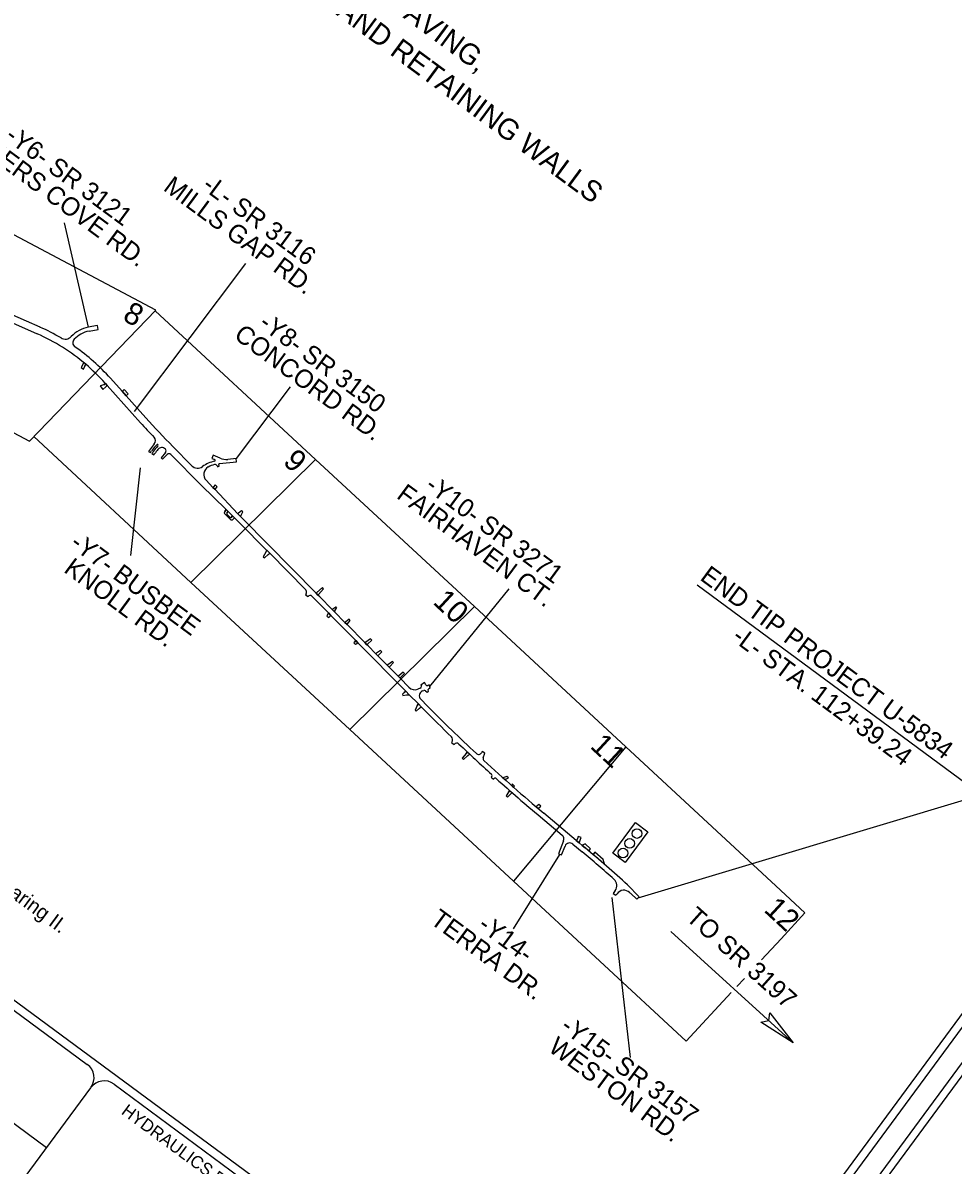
# Model space of a CAD drawing. Extents: x 945666 to 965748, y 644452 to 663300.
# Drawn here: x 956642 to 962231, y 648072 to 654930 of the extents above; entities that cross this region are included whole.
import ezdxf

# ---------------------------------------------------------------- set-up
doc = ezdxf.new("R2010")
doc.units = 0
for name, color, linetype in [('Old_Level_23', 7, 'Continuous'), ('Prop EOT', 7, 'Continuous'), ('Prop PHM Traffic Signal CELL', 7, 'Continuous'), ('Prop Shade Light', 7, 'Continuous'), ('Prop Terminator CELL', 7, 'Continuous'), ('Sheet Data Field CELL', 7, 'Continuous'), ('Sheet Plan Layout CELL', 7, 'Continuous'), ('Sheet Plot Border Inside CELL', 7, 'Continuous'), ('Sheet Plot Border Outside CELL', 7, 'Continuous'), ('Sheet Title CELL', 7, 'Continuous')]:
    doc.layers.add(name, color=color, linetype=linetype)

msp = doc.modelspace()

# ---------------------------------------------------------------- linework, layer by layer
at = {"layer": 'Old_Level_23'}
for p, q in [((956889.9, 653730), (957035, 653102.4)), ((957979.3, 653485.3), (957310.1, 652597.3)), ((958247.3, 652744.8), (957923.2, 652314.7)), ((957347.4, 652259), (957289.4, 651732.8)), ((959561.1, 651532.1), (959085.7, 650945.3)), ((959590.4, 649490.6), (959867.5, 649936)), ((960293.3, 648719.1), (960182.8, 649678.4)), ((960534.7, 649473.8), (961270.1, 648807.2))]:
    msp.add_line(p, q, dxfattribs=at)
msp.add_lwpolyline([(960337.8, 649676.2), (962398, 650295.8), (960692.6, 651553.5)], dxfattribs=at)
at = {"layer": 'Prop EOT'}
for p, q in [((957002.3, 652878.7), (957008.2, 652890.1)), ((957014.5, 652868.4), (957020.5, 652880)), ((957129.1, 652756.3), (957138.4, 652764.6)), ((957139.8, 652744.4), (957148.9, 652752.9)), ((957241.9, 652721.2), (957238.2, 652717.9)), ((957266, 652694.4), (957262.4, 652690.9)), ((957787.5, 652144.7), (957784, 652141.2)), ((957798.5, 652133.1), (957794.9, 652129.6)), ((957856.4, 651996.5), (957863, 652007.5)), ((957867.9, 651985.3), (957874.7, 651996.2)), ((957893.1, 651960.8), (957902.2, 651969.4)), ((957904.6, 651949.6), (957914.2, 651957.7)), ((957938.4, 651985.6), (957934.4, 651982.5)), ((957952.1, 651971.1), (957949.5, 651966.6)), ((958101.4, 651751.6), (958107.4, 651763.3)), ((958115.5, 651737.4), (958125.3, 651745.2)), ((958407.2, 651509.5), (958403.2, 651506.5)), ((958418.5, 651498.1), (958415.1, 651494.4)), ((958472.9, 651375.3), (958479.1, 651386.9)), ((958505, 651410.5), (958500.5, 651407.9)), ((958516.2, 651399.1), (958513.5, 651394.8)), ((958484.2, 651363.9), (958493, 651372.8)), ((958581.4, 651333.2), (958577.2, 651330.3)), ((958592.7, 651321.8), (958589.5, 651317.8)), ((958634, 651212.2), (958641.5, 651222.5)), ((958645.3, 651200.8), (958655.3, 651208.4)), ((958701.7, 651211.3), (958697.1, 651208.8)), ((958712.9, 651199.9), (958709.2, 651196.5)), ((958767.4, 651144.8), (958763.1, 651142)), ((958778.6, 651133.4), (958775.3, 651129.6)), ((958834.8, 651076.5), (958830.6, 651073.6)), ((958846.1, 651065.1), (958843.1, 651060.9)), ((958899.9, 651010.5), (958896.1, 651007.3)), ((958911.2, 650999.1), (958908, 650995.2)), ((958933.5, 650909), (958942, 650918.2)), ((958947.5, 650894.7), (958963.5, 650896.4)), ((959010.9, 650830.6), (959018, 650841.1)), ((959024.9, 650816.3), (959034.6, 650824.3)), ((959304.3, 650542.9), (959312.2, 650552.6)), ((959315.9, 650532), (959325.4, 650540.2)), ((959531.4, 650399.1), (959526, 650397.3)), ((959543.4, 650388.4), (959538.4, 650386.2)), ((959559.7, 650310.6), (959566.5, 650321.3)), ((959571.7, 650300.1), (959580.8, 650308.7)), ((959580.8, 650355.4), (959578.4, 650350.8)), ((959592.8, 650344.8), (959589, 650341.4)), ((959729.9, 650226.5), (959725.9, 650223.4)), ((959742.1, 650216.2), (959738.6, 650212.6)), ((959970.3, 650025.5), (959966.8, 650021.7)), ((959985.5, 650012.5), (959983.8, 650007.4)), ((960007.3, 649994.3), (960002.6, 649991.7)), ((960045.6, 649962.2), (960042.7, 649958)), ((960070.2, 649941.4), (960066.7, 649937.7)), ((960134.6, 649885.9), (960137, 649877.4))]:
    msp.add_line(p, q, dxfattribs=at)
at = {"layer": 'Prop PHM Traffic Signal CELL'}
for p, q in [((960186.2, 649944.1), (960322.1, 650128.4)), ((960322.1, 650128.4), (960396.6, 650073.5)), ((960396.6, 650073.5), (960260.7, 649889.2)), ((960260.7, 649889.2), (960186.2, 649944.1))]:
    msp.add_line(p, q, dxfattribs=at)
for centre in [(960331.1, 650062.6), (960287.6, 650003.6), (960247.5, 649945.5)]:
    msp.add_circle(centre, 28.8, dxfattribs=at)
at = {"layer": 'Prop Shade Light'}
for p, q in [((955896.2, 653431.8), (956727.8, 653063.6)), ((956745.2, 653103), (956582.5, 653175)), ((957090, 653113.1), (957035, 653102.5)), ((957094.6, 653089.6), (957090, 653113.1)), ((957039.5, 653078.9), (957094.6, 653089.6)), ((957002.3, 652878.7), (956993.2, 652861.5)), ((957008.2, 652890.1), (957002.3, 652878.7)), ((957014.5, 652868.4), (957020.4, 652879.8)), ((957020.5, 652880), (957020.4, 652879.8)), ((957138.3, 652764.7), (957129.1, 652756.3)), ((957148.8, 652753), (957138.3, 652764.7)), ((957129.1, 652756.3), (957106.4, 652751.1)), ((957106.4, 652751.1), (957123.3, 652729.6)), ((957123.3, 652729.6), (957139.8, 652744.4)), ((957139.8, 652744.4), (957148.8, 652753)), ((957241.9, 652721.2), (957238.2, 652717.9)), ((957238.2, 652717.9), (957262.4, 652690.9)), ((957250.3, 652728.7), (957241.9, 652721.2)), ((957274.3, 652702), (957250.3, 652728.7)), ((957262.4, 652690.9), (957265.9, 652694.4)), ((957265.9, 652694.4), (957274.3, 652702)), ((957402.4, 652364), (957397.9, 652357.4)), ((957397.9, 652357.4), (957409.4, 652349.5)), ((957409.4, 652349.5), (957413.9, 652356.1)), ((957422.2, 652350.5), (957417.7, 652343.9)), ((957431.5, 652401.6), (957427.4, 652396.7)), ((957438, 652387.7), (957446.2, 652397.2)), ((957453.8, 652390.7), (957445.6, 652381.2)), ((957499.2, 652351.2), (957473.1, 652318.5)), ((957657, 652271.4), (957542.8, 652387)), ((957417.7, 652343.9), (957429.2, 652336)), ((957429.2, 652336), (957433.8, 652342.6)), ((957473.1, 652318.5), (957480.8, 652310.7)), ((957480.8, 652310.7), (957509.1, 652338.6)), ((957530.3, 652338.5), (957712.8, 652153.7)), ((957786.1, 652334.9), (957776.7, 652313.6)), ((957776.7, 652313.6), (957794.4, 652308.6)), ((957827, 652317), (957786.1, 652334.9)), ((957820.7, 652267.8), (957818.7, 652277.8)), ((957823, 652283.8), (957925.3, 652294.8)), ((957923.2, 652314.7), (957874.1, 652309.4)), ((957925.3, 652294.8), (957923.2, 652314.7)), ((957811, 652268.4), (957812.1, 652265.3)), ((957812.1, 652265.3), (957820.7, 652267.8)), ((957787.4, 652144.7), (957783.9, 652141.2)), ((957783.9, 652141.2), (957794.9, 652129.6)), ((957798.3, 652155.5), (957787.4, 652144.7)), ((957809.5, 652144.1), (957798.3, 652155.5)), ((957798.5, 652133.1), (957809.5, 652144.1)), ((957794.9, 652129.6), (957798.5, 652133.1)), ((957863, 652007.5), (957856.4, 651996.5)), ((957874.7, 651996.2), (957863, 652007.5)), ((957856.4, 651996.5), (957850.6, 651987.1)), ((957850.6, 651987.1), (957887.7, 651949.6)), ((957867.9, 651985.3), (957874.7, 651996.2)), ((957887.9, 651960.8), (957867.9, 651981)), ((957902.2, 651969.4), (957893.1, 651960.8)), ((957914.2, 651957.7), (957902.2, 651969.4)), ((957904.6, 651949.6), (957914.2, 651957.7)), ((957938.4, 651985.7), (957934.4, 651982.6)), ((957934.4, 651982.6), (957949.5, 651966.6)), ((957949.5, 651966.6), (957952.1, 651971.1)), ((957945.7, 651927), (958105.8, 651764.9)), ((958107.4, 651763.3), (958101.4, 651751.6)), ((958125.2, 651745.3), (958107.4, 651763.3)), ((958115.5, 651737.4), (958125.2, 651745.3)), ((958441.2, 651539.3), (958407.2, 651509.5)), ((958418.5, 651498.1), (958447.8, 651532.3)), ((958447.8, 651532.3), (958441.2, 651539.3)), ((958344.4, 651502.8), (958341, 651496.6)), ((958341, 651496.6), (958355.9, 651486.3)), ((958378.9, 651488.4), (958457.8, 651408.4)), ((958407.2, 651509.5), (958403.2, 651506.5)), ((958403.2, 651506.5), (958415.1, 651494.4)), ((958415.1, 651494.4), (958418.5, 651498.1)), ((958479.1, 651387), (958472.9, 651375.4)), ((958493, 651372.8), (958479.1, 651387)), ((958505, 651410.5), (958500.5, 651408)), ((958500.5, 651408), (958513.4, 651394.8)), ((958513.4, 651394.8), (958516.2, 651399.1)), ((958516.2, 651399.1), (958528.8, 651418.9)), ((958484.2, 651364), (958493, 651372.8)), ((958581.4, 651333.2), (958577.1, 651330.3)), ((958577.1, 651330.3), (958589.5, 651317.8)), ((958602.5, 651348.9), (958581.4, 651333.2)), ((958589.5, 651317.8), (958592.6, 651321.9)), ((958592.6, 651321.9), (958609.1, 651342.8)), ((958609.1, 651342.8), (958602.5, 651348.9)), ((958634, 651212.2), (958630.8, 651207.5)), ((958641.4, 651222.5), (958634, 651212.2)), ((958655.3, 651208.4), (958641.4, 651222.5)), ((958645.3, 651200.8), (958655.3, 651208.4)), ((958701.6, 651211.3), (958697.1, 651208.8)), ((958697.1, 651208.8), (958709.2, 651196.6)), ((958730, 651230.9), (958701.6, 651211.3)), ((958709.2, 651196.6), (958712.9, 651200)), ((958712.9, 651200), (958737.5, 651223.2)), ((958737.5, 651223.2), (958730, 651230.9)), ((958767.4, 651144.8), (958763.1, 651142)), ((958763.1, 651142), (958775.3, 651129.7)), ((958791.2, 651161.4), (958767.4, 651144.8)), ((958775.3, 651129.7), (958778.6, 651133.4)), ((958778.6, 651133.4), (958799.4, 651153.1)), ((958799.4, 651153.1), (958791.2, 651161.4)), ((958834.8, 651076.5), (958830.6, 651073.7)), ((958830.6, 651073.7), (958843.1, 651061)), ((958862.7, 651096.5), (958834.8, 651076.5)), ((958843.1, 651061), (958846.1, 651065.1)), ((958846.1, 651065.1), (958868.5, 651090.6)), ((958868.5, 651090.6), (958862.7, 651096.5)), ((958899.9, 651010.5), (958896.1, 651007.3)), ((958896.1, 651007.3), (958908, 650995.2)), ((958926.3, 651032), (958899.9, 651010.5)), ((958908, 650995.2), (958911.2, 650999.2)), ((958911.2, 650999.2), (958934.7, 651023.5)), ((958934.7, 651023.5), (958926.3, 651032)), ((958933.4, 650909), (958923.6, 650899.7)), ((958941.9, 650918.2), (958933.4, 650909)), ((958963.4, 650896.4), (958941.9, 650918.2)), ((959029.7, 650935.2), (959014.2, 650929.5)), ((959054.5, 650969), (959033.5, 650953.2)), ((959033.5, 650953.2), (959035.9, 650947.2)), ((959043, 650918.8), (959051.4, 650921.9)), ((959062.6, 650955.9), (959054.5, 650969)), ((959061.1, 650920.4), (959070.1, 650911.3)), ((959070.1, 650911.3), (959079.8, 650916.1)), ((959082.2, 650954.7), (959074.6, 650951.9)), ((959079.8, 650916.1), (959076.8, 650927.2)), ((959080, 650932.6), (959089.1, 650935.9)), ((959089.1, 650935.9), (959082.2, 650954.7)), ((958923.6, 650899.7), (958925.5, 650892.1)), ((958925.5, 650892.1), (958947.5, 650894.8)), ((958947.5, 650894.8), (958963.4, 650896.4)), ((959018, 650841.2), (959010.9, 650830.6)), ((959034.6, 650824.3), (959018, 650841.2)), ((959073.1, 650828.1), (959032.1, 650869.6)), ((959004.9, 650798.3), (959024.9, 650816.4)), ((959024.9, 650816.4), (959034.6, 650824.3)), ((959219.6, 650611.9), (959217.6, 650608.9)), ((959217.6, 650608.9), (959232.2, 650597.9)), ((959304.3, 650543), (959280.9, 650515.8)), ((959290.1, 650507.6), (959315.9, 650532)), ((959312.2, 650552.6), (959304.3, 650543)), ((959315.9, 650532), (959325.4, 650540.2)), ((959401.2, 650554.9), (959397.6, 650548.2)), ((959416.6, 650545), (959401.2, 650554.9)), ((959407.6, 650516.6), (959416.6, 650545)), ((959458.5, 650404.3), (959455.7, 650401.1)), ((959455.7, 650401.1), (959469.3, 650389.3)), ((959469.3, 650389.3), (959471.7, 650392.1)), ((959531.4, 650399.1), (959526, 650397.3)), ((959548.9, 650404.8), (959531.4, 650399.1)), ((959538.4, 650386.2), (959543.4, 650388.4)), ((959543.4, 650388.4), (959559.3, 650396.8)), ((959559.3, 650396.8), (959548.9, 650404.8)), ((959559.7, 650310.7), (959545.1, 650288.7)), ((959566.5, 650321.3), (959559.7, 650310.7)), ((959571.7, 650300.1), (959580.8, 650308.7)), ((959580.7, 650355.4), (959578.4, 650350.8)), ((959589, 650341.4), (959592.8, 650344.8)), ((959729.9, 650226.6), (959725.9, 650223.4)), ((959741.6, 650237.6), (959729.9, 650226.6)), ((959738.6, 650212.6), (959742.1, 650216.2)), ((959751.6, 650162.5), (959882, 650053.4)), ((959890.6, 650019.1), (959859, 649941.7)), ((959970.2, 650025.5), (959966.7, 650021.7)), ((959966.7, 650021.7), (959983.8, 650007.4)), ((959995.6, 650039.6), (959978.4, 650045.5)), ((959985.5, 650012.6), (959995.6, 650039.6)), ((959877.5, 649934.1), (959899.4, 649987.9)), ((959946.5, 649999.5), (960001.4, 649953.6)), ((959983.8, 650007.4), (959985.5, 650012.6)), ((960007.2, 649994.3), (960002.6, 649991.7)), ((960002.6, 649991.7), (960020.6, 649976.6)), ((960019.3, 650000.1), (960007.2, 649994.3)), ((960052.8, 649971.4), (960019.3, 650000.1)), ((960042.7, 649958.1), (960045.6, 649962.2)), ((960045.6, 649962.2), (960052.8, 649971.4)), ((960077.7, 649950), (960070.2, 649941.4)), ((960127.8, 649907), (960077.7, 649950)), ((959859, 649941.7), (959877.5, 649934.1)), ((960070.2, 649941.4), (960066.7, 649937.8)), ((960134.6, 649886), (960127.8, 649907)), ((960136.9, 649877.4), (960134.6, 649886)), ((960344.7, 649683.7), (960274.5, 649754.9)), ((960200.9, 649720.7), (960188.6, 649703.8)), ((960188.6, 649703.8), (960204.8, 649692)), ((960204.8, 649692), (960211.8, 649701.6)), ((960293.7, 649702.1), (960330.9, 649668.9)), ((960330.9, 649668.9), (960344.7, 649683.7))]:
    msp.add_line(p, q, dxfattribs=at)
for points in [[(956993.2, 652861.5), (957007.2, 652851.1), (957014.5, 652868.4)], [(957020.4, 652879.9), (957020.5, 652880)], [(957135.9, 652767.4), (957138.3, 652764.7), (957148.8, 652753), (957349.6, 652529.5)], [(957381.5, 652558.3), (957262.4, 652690.9), (957238.2, 652717.9), (957167.9, 652796.1)], [(957498.2, 652371.1), (957498.3, 652371)], [(957712.8, 652153.7), (957863, 652007.5), (957874.7, 651996.2), (957902.2, 651969.4), (957914.2, 651957.7), (957945.7, 651927)], [(957967.1, 651948.1), (957949.5, 651966.6), (957934.4, 651982.6), (957794.9, 652129.6), (957783.9, 652141.2), (957743.4, 652183.9)], [(957783.9, 652141.2), (957783.9, 652141.2)], [(957952.1, 651971.1), (957964.1, 651994), (957955.9, 651999.8), (957938.4, 651985.7)], [(958425.5, 651483.9), (958415.1, 651494.4), (958403.2, 651506.5), (957967.1, 651948.1)], [(958101.4, 651751.6), (958086.7, 651723.6), (958092.8, 651718.5), (958115.5, 651737.4)], [(958105.8, 651764.9), (958107.4, 651763.3), (958125.2, 651745.3), (958341.2, 651526.6)], [(958589.5, 651317.8), (958577.1, 651330.3), (958513.4, 651394.8), (958500.5, 651408), (958425.5, 651483.9)], [(958457.8, 651408.4), (958479.1, 651387), (958493, 651372.8), (958641.4, 651222.5), (958655.3, 651208.4), (958941.9, 650918.2), (958963.4, 650896.4), (959018, 650841.2), (959034.6, 650824.3), (959051.8, 650807)], [(958528.8, 651418.9), (958521.9, 651422.5), (958505, 651410.5)], [(958472.9, 651375.4), (958468.8, 651367.4), (958479.2, 651359.4), (958484.2, 651364)], [(958716.4, 651189.3), (958709.2, 651196.6), (958697.1, 651208.8), (958589.5, 651317.8)], [(958630.8, 651207.5), (958640.1, 651197.9), (958645.3, 651200.8)], [(958961.3, 650941.3), (958908, 650995.2), (958896.1, 651007.3), (958843.1, 651061), (958830.6, 651073.7), (958775.3, 651129.7), (958763.1, 651142), (958716.4, 651189.3)], [(959010.9, 650830.6), (958997.9, 650804), (959004.9, 650798.3)], [(959280.9, 650515.8), (959284.6, 650511.5), (959290.1, 650507.6)], [(959592.8, 650344.8), (959596.4, 650347.4), (959581, 650361.5), (959580.7, 650355.4)], [(959545.1, 650288.7), (959553.5, 650281.9), (959571.7, 650300.1)], [(959742.1, 650216.2), (959753.8, 650227.3), (959741.6, 650237.6)], [(960020.6, 649976.6), (960002.6, 649991.7), (959983.8, 650007.4), (959966.7, 650021.7), (959770.9, 650185.6)]]:
    msp.add_lwpolyline(points, dxfattribs=at)
for centre, radius, start, end in [((956240.5, 651963.2), 1246.5, 59.59437, 66.11932), ((957071.5, 652914), 192, 100.975, 136.23687), ((956240.5, 651963.2), 1203.5, 49.61225, 66.11932), ((956896.7, 653081.4), 50, 239.59437, 316.23687), ((957071.5, 652914), 168, 100.975, 136.2327), ((956971.8, 653009.4), 30, 136.2327, 235.04773), ((956240.5, 651963.2), 1246.5, 41.93071, 55.04773), ((956240.5, 651963.2), 1203.5, 49.60968, 50.37119), ((956240.5, 651963.2), 1203.5, 41.93071, 49.60968), ((961085.3, 655885), 4978.5, 221.93071, 224.63859), ((961085.3, 655885), 5021.5, 221.93071, 223.2943), ((957408.6, 652421), 30, 319.6, 43.2943), ((957723.6, 652144.6), 389, 139.6, 145.66667), ((957723.6, 652144.6), 375, 139.6, 145.66667), ((957723.6, 652144.6), 365, 139.6, 145.66667), ((957723.6, 652144.6), 351, 140.22989, 145.66667), ((957450, 652394), 5, 319.6, 139.6), ((957476.9, 652350), 30, 44.61179, 140.22989), ((957487.5, 652360.6), 15, 44.12626, 44.40966), ((957476.9, 652350), 30, 44.4117, 44.61179), ((957487.5, 652360.6), 15, 321.50181, 44.12626), ((957519.6, 652327.9), 15, 44.63859, 134.59178), ((957843.5, 652094.8), 210, 103.58043, 125.48912), ((957843.5, 652094.8), 190, 105.46909, 117.46274), ((957796.8, 652263.5), 15, 18.91701, 105.46909), ((957793, 652303.8), 5, 283.58043, 74.24747), ((957823.6, 652278.8), 5, 96.42397, 191.37306), ((957864.4, 652398.9), 90, 245.40579, 276.18333), ((957692.6, 652306.5), 50, 224.63859, 305.48912), ((957778.9, 652219.1), 50, 117.46274, 224.63859), ((957870.1, 651983.2), 3.12, 135.78436, 224.63859), ((957896.1, 651957.9), 11.8, 224.63859, 315.78436), ((957890.5, 651963.4), 3.69, 224.63859, 315.78436), ((958326.9, 651512.5), 20, 330.7607, 44.63859), ((958368.2, 651477.8), 15, 44.63859, 145.45268), ((958996.9, 650976.4), 50, 224.63859, 290.31711), ((959053.4, 650890.7), 30, 110.31711, 224.63859), ((959026.2, 650944.6), 10, 290.31711, 15.019), ((959054.8, 650912.6), 10, 51.42192, 110.31711), ((959071.1, 650961.2), 10, 212.07076, 290.31711), ((959081.8, 650927.9), 5, 110.31711, 187.71299), ((966178, 657843.8), 10015, 224.63859, 225.9637), ((966178, 657843.8), 9985, 224.63859, 226.98518), ((959199, 650626.1), 25, 325.51934, 45.9637), ((959248.1, 650585.8), 20, 46.32509, 142.96717), ((966178, 657843.8), 10015, 226.32509, 227.85403), ((966178, 657843.8), 10015, 226.72127, 226.82512), ((959380, 650557.7), 20, 226.98518, 331.90862), ((959421.8, 650512), 15, 162.28522, 227.34006), ((966178, 657843.8), 9985, 227.34006, 230.08333), ((959451, 650410.9), 10, 318.83333, 47.85403), ((959479.2, 650385.5), 10, 48.07123, 138.83333), ((966178, 657843.8), 10015, 228.07123, 230.08333), ((966178, 657843.8), 9985, 228.22565, 228.32103), ((966178, 657843.8), 10015, 228.68811, 228.7973), ((966178, 657843.8), 9985, 228.62739, 228.70893), ((966178, 657843.8), 9985, 229.74594, 229.84179), ((959862.8, 650030.4), 30, 337.7936, 50.08333), ((959948.4, 650046), 30, 316.83583, 359.09599), ((959927.2, 649976.5), 30, 50.08333, 157.7936), ((954877.6, 643829.3), 7985, 48.25902, 50.08333), ((954877.6, 643829.3), 8015, 47.67351, 50.08333), ((954877.6, 643829.3), 8015, 49.87729, 50.08333), ((954877.6, 643829.3), 8015, 48.99034, 49.65257), ((960160.5, 649750.1), 50, 324.0667, 48.25902), ((960252.3, 649672.3), 50, 47.39074, 144.0667), ((954877.6, 643829.3), 7989, 47.31687, 47.39074)]:
    msp.add_arc(centre, radius, start, end, dxfattribs=at)
at = {"layer": 'Prop Terminator CELL'}
msp.add_lwpolyline([(961129.4, 648987), (961270.1, 648807.2), (961075.6, 648929.5), (961123.8, 648939.9)], close=True, dxfattribs=at)
at = {"layer": 'Sheet Plan Layout CELL'}
for p, q in [((957441.2, 653205.6), (956320.5, 653797.4)), ((957441.2, 653205.6), (956681.5, 652419.4)), ((958399.9, 652309.4), (957436.9, 653201.2)), ((955894.4, 652835), (956681.5, 652419.4)), ((956707.1, 652446), (957652.1, 651570.9)), ((958399.9, 652309.4), (957652.1, 651570.9)), ((959354.7, 651425.3), (958399.9, 652309.4)), ((957652.1, 651570.9), (958606.8, 650686.8)), ((959354.7, 651425.3), (958606.8, 650686.8)), ((960263.7, 650583.5), (959354.7, 651425.3)), ((958606.8, 650686.8), (959589.1, 649777.2)), ((960263.7, 650583.5), (959589.1, 649777.2)), ((961164.9, 649749), (960263.7, 650583.5)), ((959589.1, 649777.2), (960627, 648816)), ((961340.5, 649586.4), (961164.9, 649749)), ((961196.8, 649431.2), (961340.5, 649586.4)), ((961079, 649304.1), (961196.8, 649431.2)), ((960627, 648816), (960897.5, 649108))]:
    msp.add_line(p, q, dxfattribs=at)
msp.add_lwpolyline([(960930.4, 649143.6), (960976.2, 649193.1)], dxfattribs=at)
at = {"layer": 'Sheet Plot Border Inside CELL'}
msp.add_lwpolyline([(945903.9, 654551), (959315.9, 644659.5), (965578.4, 653150.9), (952166.4, 663042.4)], close=True, dxfattribs=at)
at = {"layer": 'Sheet Plot Border Outside CELL'}
msp.add_lwpolyline([(965747.9, 653304.9), (952195, 663300.2), (945666.1, 654447.6), (959218.9, 644452.2)], close=True, dxfattribs=at)
at = {"layer": 'Sheet Title CELL'}
for p, q in [((948809.3, 654800.8), (960237.5, 646372.5)), ((954735.2, 650368.4), (957028.9, 648676.7)), ((956784.3, 648176.7), (954329.7, 649987.1)), ((956100.2, 647249.1), (957049.9, 648536.8)), ((957189.8, 648558), (958797.6, 647372.3))]:
    msp.add_line(p, q, dxfattribs=at)
for points in [[(959289.8, 644834.8), (965403.3, 653124.1)], [(960377.3, 646393.5), (965333.4, 653113.7)]]:
    msp.add_lwpolyline(points, dxfattribs=at)
for centre, start, end in [((956969.8, 648596.6), 323.59084, 53.59084), ((957130.8, 648477.9), 53.59084, 143.59084)]:
    msp.add_arc(centre, 100, start, end, dxfattribs=at)

# ---------------------------------------------------------------- texts
at = {"layer": 'Old_Level_23'}
for s, rotation, p in [('PINNERS COVE RD.', 323.59084, (956205.2, 654293)), ('-Y6- SR 3121', 323.59084, (956529.1, 654233.4)), ('MILLS GAP RD.', 323.59084, (957480.1, 653928.9)), ('-L- SR 3116', 323.59084, (957712, 653937)), ('CONCORD RD.', 323.59084, (957903.8, 653040.3)), ('-Y8- SR 3150', 323.59084, (958052.8, 653109.6)), ('FAIRHAVEN CT.', 323.59084, (958881.1, 652081)), ('-Y10- SR 3271', 323.59084, (959051.8, 652134.4)), ('-Y7- BUSBEE', 323.59084, (956919, 651788.8)), ('KNOLL RD.', 323.59084, (956882, 651636.9)), (' END TIP PROJECT U-5834', 323.59084, (960671.1, 651613.9)), ('-L- STA. 112+39.24', 323.59084, (960895.2, 651226.6)), ('TERRA DR.', 323.59084, (959082.8, 649527.7)), ('TO SR 3197', 318.19631, (960619.5, 649549.3)), ('-Y14-', 323.59084, (959368.7, 649496.1)), ('-Y15- SR 3157', 323.59084, (959864.6, 648887.2)), ('WESTON RD.', 323.59084, (959791.6, 648761.8))]:
    msp.add_text(s, height=110, rotation=rotation, dxfattribs=at).set_placement(p)
at = {"layer": 'Sheet Data Field CELL'}
for s, height, p in [('GRADING, DRAINAGE, PAVING,', 125.001, (957351.9, 656121.9)), ('SIGNALS, SIGNING, AND RETAINING WALLS', 125.001, (957218.4, 655940.7)), ('Clearing on this project shall be performed to the limits established by the Method of Clearing II.', 87.501, (952885.5, 652396.6))]:
    msp.add_text(s, height=height, rotation=323.59084, dxfattribs=at).set_placement(p)
at = {"layer": 'Sheet Plan Layout CELL'}
for s, height, rotation, p in [('8', 131.3, 332.16444, (957234.9, 653147.3)), ('9', 131.3, 317.19913, (958198.9, 652287.4)), ('10', 131.25, 317.19913, (959099.7, 651446.2)), ('11', 131.25, 317.19913, (960044.1, 650580.7)), ('12', 131.25, 317.19913, (961088, 649598.5))]:
    msp.add_text(s, height=height, rotation=rotation, dxfattribs=at).set_placement(p)
at = {"layer": 'Sheet Title CELL'}
msp.add_text(' HYDRAULICS ENGINEER', height=75, rotation=323.59084, dxfattribs=at).set_placement((957206.1, 648399.9))

doc.saveas('drawing.dxf')
